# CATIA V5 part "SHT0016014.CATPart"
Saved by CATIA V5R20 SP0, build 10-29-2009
Part number: SHT0016014.2
Source: Unknown
Bounding box of the stored display mesh (mm): x -544.085 to 25.758, y -866.5 to -591.5, z 0.9 to 106.4
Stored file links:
  F:\福田A6\1-数据\6-冻结数据\第九批\设变\静电导线设变\SHT0016014-宽车主驾驶底部支架焊接总成\更改后数据\SHT0016014-宽车主驾驶底部支架焊接总成\SHT0016014.CATPart

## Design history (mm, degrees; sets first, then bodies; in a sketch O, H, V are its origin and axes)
Set1
  Point1 to Point4: stored without definition
Body1 "几何体" (main body)
Body2 "SHT0016151-支撑轴套"
  Solid1: solid without history
Body3 "SHT0016151-支撑轴套"
  Solid2: solid without history
Body4 "SHT0016151-支撑轴套"
  Solid3: solid without history
Body5 "SHT0016014.1\\SHT0016145-宽车主驾驶前侧钣金"
  Solid4: solid without history
Body6 "SHT0016014.1\\SHT0016148-宽车主驾驶左侧钣金"
  Solid5: solid without history
Body7 "SHT0016014.1\\SHT0016148-宽车主驾驶左侧钣金"
  Solid6: solid without history
Body8 "SHT0016151-支撑轴套"
  Solid7: solid without history
Body9 "SHT0016014.1\\Q37108-焊接方螺母"
  Solid8: solid without history
Body10 "SHT0016014.1\\Q37108-焊接方螺母"
  Solid9: solid without history
Body11 "SHT0016014.1\\Q37108-焊接方螺母"
  Solid10: solid without history
Body12 "SHT0016014.1\\Q37108-焊接方螺母"
  Solid11: solid without history
Body13 "SHT0016014.1\\Q37108-焊接方螺母"
  Solid12: solid without history
Body14 "SHT0016014.1\\Q37108-焊接方螺母"
  Solid13: solid without history
Body15 "SHT0016014.1\\Q37106-焊接方螺母"
  Solid14: solid without history
Body16 "SHT0016014.1\\Q37110-焊接方螺母"
  Solid15: solid without history
Body17 "SHT0016014.1\\Q37110-焊接方螺母"
  Solid16: solid without history
Body18 "SHT0016014.1\\Q37106-焊接方螺母"
  Solid17: solid without history
Body19 "SHT0016014.1\\Q37106-焊接方螺母"
  Solid18: solid without history
Body20 "SHT0016014.1\\Q37106-焊接方螺母"
  Solid19: solid without history
Body21 "SHT0016014.1\\SHT0016146-宽车主驾驶后侧钣金"
  Solid20: solid without history
Body22 "Q37108-焊接方螺母"
  Solid21: solid without history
